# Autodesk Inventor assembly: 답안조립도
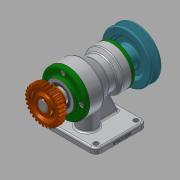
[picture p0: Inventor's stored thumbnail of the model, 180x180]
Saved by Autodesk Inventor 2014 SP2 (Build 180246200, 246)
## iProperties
Created: 2019-01
Part Number: 답안조립도
Document SubType Name: Assembly
Designer: CM-CAD
Author: CM-CAD
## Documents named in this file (15)
- C:\Users\cm\Desktop\490107V1011\답안조립도.iam
- C:\Users\cm\Desktop\490107V1011\본체.ipt
- C:\Users\cm\Desktop\490107V1011\베어링 6203.ipt
- C:\Users\cm\Desktop\490107V1011\베어링 6205.ipt
- C:\Users\cm\Desktop\490107V1011\뒤커버.ipt
- C:\Users\cm\Desktop\490107V1011\앞커버.ipt
- C:\Users\cm\Desktop\490107V1011\볼트 M4.ipt
- C:\Users\cm\Desktop\490107V1011\오일 실 17 30 8.ipt
- C:\Users\cm\Desktop\490107V1011\오일 실 25 38 8.ipt
- C:\Users\cm\Desktop\490107V1011\축.ipt
- C:\Users\cm\Desktop\490107V1011\키 6 x 6 x 18.ipt
- C:\Users\cm\Desktop\490107V1011\키 5 x 5 x 20.ipt
- C:\Users\cm\Desktop\490107V1011\V-벨트풀리.ipt
- C:\Users\cm\Desktop\490107V1011\스퍼기어.ipt
- C:\Users\cm\Desktop\490107V1011\멈춤나사 M3.ipt
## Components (1 placed, 1 different names)
1. V-벨트풀리:1
